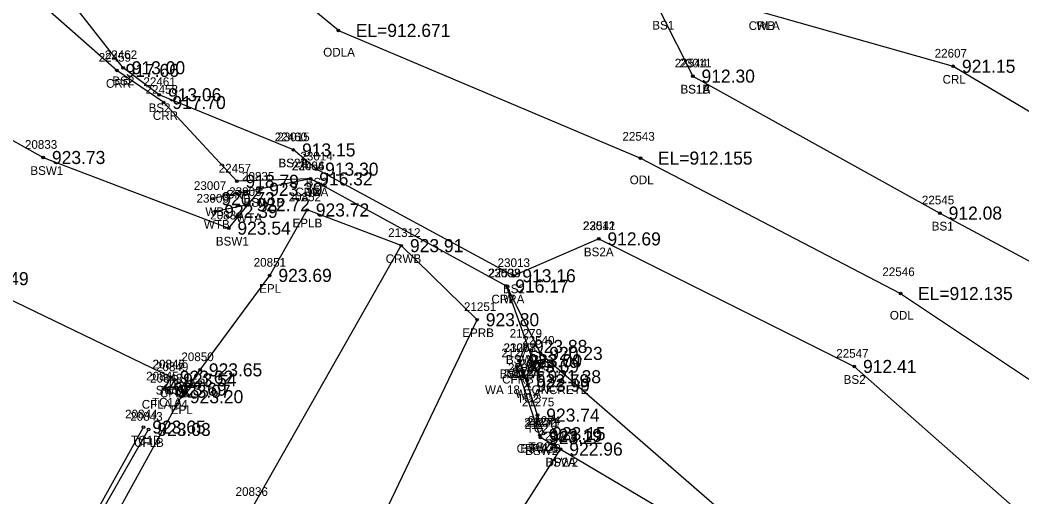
# Model space of a CAD drawing. Extents: x 1576181 to 1577685, y 1099396 to 1101490.
# Drawn here: x 1576844.5 to 1576959.6, y 1100377.3 to 1100432.1 of the extents above; entities that cross this region are included whole.
import ezdxf

# ---------------------------------------------------------------- set-up
doc = ezdxf.new("R2010")
doc.units = 0
for name, color, linetype in [('RD_DTM_BkLn1', 7, 'Continuous'), ('RD_DTM_BkLn2', 7, 'Continuous'), ('RD_DTM_BkLn_txCode', 7, 'Continuous'), ('RD_EX_BldgApp', 7, 'Continuous'), ('RD_EX_Conc', 7, 'Continuous'), ('RD_EX_Conc_txCode', 7, 'Continuous'), ('RD_EX_Driveway', 7, 'Continuous'), ('RD_EX_Driveway_txCode', 7, 'Continuous'), ('RD_EX_H2O', 7, 'Continuous'), ('RD_EX_H2O_txCode', 7, 'Continuous'), ('RD_EX_Misc_txCode', 7, 'Continuous'), ('RD_EX_Road', 7, 'Continuous'), ('RD_EX_Road_txCode', 7, 'Continuous'), ('RD_EX_TX_Conc_ELEV', 7, 'Continuous'), ('RD_EX_TX_Driveway_ELEV', 7, 'Continuous'), ('RD_EX_TX_H2O_ELEV', 7, 'Continuous'), ('RD_EX_TX_Misc_ELEV', 7, 'Continuous'), ('RD_EX_TX_Road_ELEV', 7, 'Continuous'), ('RD_HC_Survey_ELEV', 7, 'Continuous'), ('RD_HC_Survey_txCode', 7, 'Continuous'), ('RD_SMD_Locator', 7, 'Continuous')]:
    doc.layers.add(name, color=color, linetype=linetype)

msp = doc.modelspace()

# ---------------------------------------------------------------- linework, layer by layer
at = {"layer": 'RD_DTM_BkLn1'}
msp.add_lwpolyline([(1576435.96, 1099635.47), (1576469.98, 1099685.91), (1576496.51, 1099728.46), (1576522.67, 1099770.85), (1576549.06, 1099813.4), (1576563.36, 1099837.2), (1576575.09, 1099855.95), (1576600.75, 1099898.96), (1576625.57, 1099942.14), (1576652.37, 1099988.91), (1576675.03, 1100029.12), (1576699.51, 1100072.44), (1576723.52, 1100115.7), (1576748.08, 1100158.53), (1576774.13, 1100203.85), (1576797.97, 1100246.52), (1576822.46, 1100289.82), (1576846.93, 1100333.35), (1576871.37, 1100376.46), (1576888.27, 1100406.22)], dxfattribs=at)
at = {"layer": 'RD_DTM_BkLn2'}
for p, q in [((1576870.64, 1100410.93), (1576866.93, 1100410.16)), ((1576902.73, 1100390.7), (1576901.89, 1100392.99)), ((1576861.07, 1100389.73), (1576861.82, 1100391.11))]:
    msp.add_line(p, q, dxfattribs=at)
for points in [[(1576875.87, 1100417.22), (1576860.46, 1100423.56), (1576856.3, 1100426.66), (1576843.23, 1100443.4), (1576803.31, 1100463.52), (1576761.44, 1100493.57), (1576725.45, 1100515.73), (1576681.3, 1100547.02), (1576635.87, 1100579.97), (1576595.08, 1100610.51), (1576554.15, 1100644.81), (1576510.62, 1100680.61), (1576466.87, 1100717.7)], [(1576886.42, 1100451.57), (1576894.91, 1100444.78), (1576918.06, 1100433.05), (1576921.77, 1100425.7)], [(1576921.77, 1100425.7), (1576950.17, 1100409.96), (1576995.01, 1100385.92), (1577032.35, 1100355.75), (1577074.98, 1100332.75), (1577110.34, 1100313.04), (1577151.78, 1100294.62), (1577183.98, 1100273.41), (1577237.32, 1100241.27), (1577274.56, 1100213.94), (1577313.28, 1100186.77), (1577349.98, 1100171.96)], [(1576910.96, 1100407), (1576901.18, 1100402.76), (1576878.52, 1100415.01), (1576875.87, 1100417.22)], [(1576896.98, 1100397.71), (1576888.27, 1100406.22), (1576877.45, 1100410.32)], [(1576910.96, 1100407), (1576940.33, 1100392.34), (1576974.42, 1100362.26), (1577019.12, 1100334.75), (1577060.03, 1100308.77), (1577094.53, 1100282.76), (1577137.68, 1100262.43), (1577168.48, 1100246.28), (1577215.8, 1100216.27), (1577257.09, 1100185.27), (1577298.12, 1100162.18), (1577331.94, 1100143.39)], [(1576904.61, 1100384.62), (1576903.93, 1100386.75), (1576902.8, 1100390.19), (1576901.82, 1100392.99)], [(1576569.71, 1099889.13), (1576574.56, 1099891.34), (1576579.27, 1099894.47), (1576584.19, 1099899.55), (1576592.25, 1099913.59), (1576612.84, 1099949.87), (1576637.54, 1099993.05), (1576637.54, 1099993.05), (1576662.19, 1100036.34), (1576686.67, 1100079.69), (1576711.46, 1100123.12), (1576735.92, 1100166.59), (1576760.76, 1100210.19), (1576785.21, 1100253.55), (1576809.13, 1100296.43), (1576833.85, 1100340.61), (1576852.06, 1100373.52), (1576858.66, 1100385.37)]]:
    msp.add_lwpolyline(points, dxfattribs=at)
at = {"layer": 'RD_EX_BldgApp'}
msp.add_lwpolyline([(1576904.09, 1100391.16), (1576900.37, 1100401.58), (1576877.84, 1100413.89), (1576866.6, 1100411.62)], dxfattribs=at)
at = {"layer": 'RD_EX_Conc'}
for p, q in [((1576901.82, 1100392.99), (1576902.52, 1100394.64)), ((1576904.2, 1100384.42), (1576901.56, 1100392.38)), ((1576861.53, 1100389.49), (1576862.21, 1100390.8))]:
    msp.add_line(p, q, dxfattribs=at)
for points in [[(1576537.53, 1099904.47), (1576543.86, 1099909.52), (1576562.16, 1099910.99), (1576591.51, 1099962.44), (1576615.66, 1100005.02), (1576615.66, 1100005.02), (1576639.95, 1100047.65), (1576665.61, 1100092.87), (1576689.57, 1100135.17), (1576714.68, 1100179.66), (1576738.99, 1100222.53), (1576763.6, 1100265.87), (1576774.84, 1100284.48), (1576788.69, 1100308.17), (1576806.14, 1100353.34), (1576815.02, 1100384.28), (1576820.35, 1100399.92), (1576825.22, 1100406.93), (1576832.15, 1100418.17), (1576835.04, 1100423.11), (1576847.13, 1100416.35), (1576868.44, 1100408.23), (1576872.09, 1100412.69)], [(1576592.25, 1099913.59), (1576580.2, 1099912.49), (1576604.17, 1099954.86), (1576628.85, 1099997.89), (1576628.85, 1099997.89), (1576652.81, 1100040.47), (1576678.28, 1100085.17), (1576702.19, 1100127.32), (1576727.43, 1100172.04), (1576752.1, 1100215.39), (1576776.49, 1100258.76), (1576788, 1100277.34), (1576801.96, 1100301.42), (1576820.18, 1100348.3), (1576829.19, 1100379.59), (1576833.87, 1100393.41), (1576838.32, 1100402.43), (1576861.82, 1100391.11)], [(1576569.87, 1099888.69), (1576574.84, 1099890.86), (1576574.84, 1099890.86), (1576579.65, 1099894.15), (1576584.72, 1099899.29), (1576592.68, 1099913.3), (1576613.45, 1099949.72), (1576638.02, 1099992.78), (1576638.02, 1099992.78), (1576662.6, 1100036.05), (1576687.14, 1100079.44), (1576711.91, 1100122.93), (1576736.42, 1100166.35), (1576761.24, 1100209.96), (1576785.67, 1100253.17), (1576809.57, 1100296.25), (1576834.31, 1100340.56), (1576852.46, 1100373.22), (1576852.46, 1100373.22), (1576859.24, 1100385.1)], [(1576899.64, 1100371.95), (1576906.58, 1100382.84), (1576904.27, 1100384.16), (1576904.2, 1100384.42)]]:
    msp.add_lwpolyline(points, dxfattribs=at)
at = {"layer": 'RD_EX_Driveway'}
msp.add_lwpolyline([(1576906.58, 1100382.84), (1576964.44, 1100348.56), (1576998.21, 1100327.41)], dxfattribs=at)
at = {"layer": 'RD_EX_H2O'}
for points in [[(1576881.04, 1100430.95), (1576850.51, 1100456.18), (1576811.02, 1100474.55), (1576770.3, 1100506.51), (1576738.8, 1100537.68), (1576691.12, 1100558.51), (1576645.69, 1100592.61), (1576611.01, 1100637.34), (1576572.36, 1100669.07), (1576520.62, 1100693.32), (1576482.36, 1100733.93)], [(1576877.84, 1100413.89), (1576869.37, 1100413.62), (1576860.97, 1100422.67), (1576855.58, 1100426.36), (1576840.87, 1100439.31), (1576798.64, 1100456.7), (1576756.83, 1100486.11), (1576719.94, 1100507.6), (1576677.18, 1100540.85), (1576627.08, 1100575.48), (1576584.18, 1100605.6), (1576548.29, 1100637.23), (1576503.87, 1100673.91), (1576459.55, 1100707.51)], [(1576929.91, 1100433), (1576951.7, 1100426.83), (1576996.53, 1100400.27), (1577038.81, 1100373.75), (1577079.67, 1100350.15), (1577122.69, 1100322.64), (1577157.62, 1100301.09), (1577195.23, 1100276.28), (1577240.04, 1100251.66), (1577278.94, 1100221.51), (1577312.77, 1100200.12), (1577352.78, 1100176.91)], [(1576881.04, 1100430.95), (1576915.76, 1100416.28), (1576945.65, 1100400.72), (1576983.21, 1100375.69), (1577026.89, 1100346.5), (1577063.53, 1100313.12), (1577099, 1100292.55), (1577141.18, 1100270.15), (1577175.83, 1100258.35), (1577225.81, 1100228), (1577268.32, 1100204.5), (1577306.36, 1100176.14), (1577339.68, 1100156.23)], [(1576900.37, 1100401.58), (1576904.28, 1100393.84), (1576927.49, 1100373.64), (1576968.41, 1100349.92), (1577010.57, 1100322.36), (1577050.41, 1100297.37), (1577087.05, 1100275.19), (1577127.2, 1100251.29), (1577165.43, 1100227.76), (1577206.9, 1100201.89), (1577246.29, 1100176.81), (1577287.62, 1100151.2), (1577327.03, 1100134.92)]]:
    msp.add_lwpolyline(points, dxfattribs=at)
at = {"layer": 'RD_EX_Road'}
for points in [[(1576574.84, 1099890.86), (1576581.17, 1099887.16), (1576595.39, 1099911.97), (1576615.87, 1099948.17), (1576640.56, 1099991.4), (1576640.56, 1099991.4), (1576664.88, 1100034.19), (1576689.84, 1100078.06), (1576714.22, 1100121.19), (1576739.08, 1100164.66), (1576764.15, 1100209.11), (1576788.31, 1100251.8), (1576812.15, 1100294.46), (1576837.06, 1100339.37), (1576855.38, 1100371.53), (1576853.98, 1100372.48), (1576862.98, 1100388.86), (1576865.16, 1100391.95), (1576873.15, 1100402.8), (1576877.45, 1100410.32)], [(1576663.31, 1099979.53), (1576687.43, 1100021.53), (1576712.03, 1100065.1), (1576738.42, 1100112.14), (1576760.61, 1100151.41), (1576785.78, 1100195.96), (1576800.59, 1100221.87), (1576817.54, 1100252.08), (1576858.25, 1100324.63), (1576880.45, 1100364.01), (1576883.5, 1100369.45), (1576896.98, 1100397.71)]]:
    msp.add_lwpolyline(points, dxfattribs=at)
at = {"layer": 'RD_SMD_Locator'}
for centre in [(1576881.04, 1100430.95), (1576881.04, 1100430.95), (1576855.58, 1100426.36), (1576856.3, 1100426.66), (1576951.7, 1100426.83), (1576921.77, 1100425.7), (1576921.77, 1100425.7), (1576860.46, 1100423.56), (1576860.97, 1100422.67), (1576875.87, 1100417.22), (1576875.87, 1100417.22), (1576847.13, 1100416.35), (1576915.76, 1100416.28), (1576878.52, 1100415.01), (1576877.84, 1100413.89), (1576877.84, 1100413.89), (1576869.37, 1100413.62), (1576872.09, 1100412.69), (1576866.6, 1100411.62), (1576870.64, 1100410.93), (1576877.45, 1100410.32), (1576866.93, 1100410.16), (1576950.17, 1100409.96), (1576868.44, 1100408.23), (1576910.96, 1100407), (1576910.96, 1100407), (1576888.27, 1100406.22), (1576873.15, 1100402.8), (1576901.18, 1100402.76), (1576900.37, 1100401.58), (1576900.37, 1100401.58), (1576945.65, 1100400.72), (1576896.98, 1100397.71), (1576902.52, 1100394.64), (1576901.82, 1100392.99), (1576901.82, 1100392.99), (1576901.89, 1100392.99), (1576904.28, 1100393.84), (1576865.16, 1100391.95), (1576901.56, 1100392.38), (1576940.33, 1100392.34), (1576861.82, 1100391.11), (1576861.82, 1100391.11), (1576862.21, 1100390.8), (1576902.73, 1100390.7), (1576904.09, 1100391.16), (1576861.07, 1100389.73), (1576861.53, 1100389.49), (1576902.8, 1100390.19), (1576862.98, 1100388.86), (1576903.93, 1100386.75), (1576858.66, 1100385.37), (1576859.24, 1100385.1), (1576904.2, 1100384.42), (1576904.2, 1100384.42), (1576904.27, 1100384.16), (1576904.61, 1100384.62), (1576906.58, 1100382.84), (1576906.58, 1100382.84)]:
    msp.add_circle(centre, 0.15, dxfattribs=at)

# ---------------------------------------------------------------- texts
at = {"layer": 'RD_DTM_BkLn_txCode'}
for s, p in [('BS1', (1576917.11, 1100431.05)), ('22462', (1576854.2, 1100427.66)), ('22544', (1576919.69, 1100426.7)), ('23011', (1576920.22, 1100426.7)), ('BS2', (1576855.07, 1100424.66)), ('22461', (1576858.64, 1100424.56)), ('BS1A', (1576920.34, 1100423.7)), ('BS1B', (1576920.36, 1100423.7)), ('BS2', (1576859.23, 1100421.56)), ('22460', (1576873.73, 1100418.22)), ('23015', (1576874.03, 1100418.22)), ('BS2A', (1576874.15, 1100415.22)), ('BS2B', (1576874.17, 1100415.22)), ('23014', (1576876.68, 1100416.01)), ('BS2', (1576877.29, 1100413.01)), ('22545', (1576948.09, 1100410.96)), ('23012', (1576909.13, 1100408)), ('22541', (1576909.17, 1100408)), ('BS1', (1576949.22, 1100407.96)), ('BS2A', (1576909.25, 1100405)), ('BS2A', (1576909.25, 1100405)), ('23013', (1576899.34, 1100403.76)), ('BS2', (1576899.95, 1100400.76)), ('22547', (1576938.25, 1100393.34)), ('BS2', (1576939.1, 1100390.34))]:
    msp.add_text(s, height=1, dxfattribs=at).set_placement(p)
at = {"layer": 'RD_EX_Conc_txCode'}
for s, p in [('20833', (1576845.02, 1100417.35)), ('BSW1', (1576845.65, 1100414.35)), ('20835', (1576869.97, 1100413.69)), ('BSW1B', (1576870.14, 1100410.69)), ('20834', (1576866.32, 1100409.23)), ('BSW1', (1576866.96, 1100406.23)), ('21279', (1576900.73, 1100395.64)), ('21273', (1576899.77, 1100393.38)), ('21277', (1576900.03, 1100393.99)), ('21278', (1576900.03, 1100393.99)), ('20846', (1576859.68, 1100392.11)), ('20847', (1576859.7, 1100392.11)), ('BSW2B', (1576900.29, 1100392.64)), ('20849', (1576860.09, 1100391.8)), ('BSW2A', (1576899.57, 1100390.99)), ('TC2B', (1576900.11, 1100390.99)), ('21276', (1576900.98, 1100391.19)), ('20845', (1576858.95, 1100390.73)), ('20848', (1576859.41, 1100390.49)), ('CFRB', (1576899.86, 1100390.38)), ('SWLB', (1576860.06, 1100389.11)), ('TC1B', (1576860.39, 1100389.11)), ('CFLB', (1576860.53, 1100388.8)), ('CFLA 24', (1576858.45, 1100387.49)), ('TC1A', (1576859.62, 1100387.73)), ('TC2', (1576901.55, 1100388.19)), ('21275', (1576902.13, 1100387.75)), ('20844', (1576856.54, 1100386.37)), ('20843', (1576857.13, 1100386.1)), ('21272', (1576902.4, 1100385.42)), ('21270', (1576902.44, 1100385.16)), ('21271', (1576902.69, 1100385.42)), ('21274', (1576902.82, 1100385.62)), ('TC2', (1576902.68, 1100384.75)), ('TC1B', (1576857.22, 1100383.37)), ('CFLB', (1576857.57, 1100383.1)), ('21264', (1576904.76, 1100383.84)), ('CFRA 6', (1576901.52, 1100382.42)), ('BSW2B', (1576901.96, 1100382.42)), ('BSW2', (1576902.51, 1100382.16)), ('TC2A', (1576902.88, 1100382.62)), ('BSW2', (1576904.82, 1100380.84))]:
    msp.add_text(s, height=1, dxfattribs=at).set_placement(p)
at = {"layer": 'RD_EX_Driveway_txCode'}
for s, p in [('21265', (1576904.76, 1100383.84)), ('DP2A', (1576904.86, 1100380.84))]:
    msp.add_text(s, height=1, dxfattribs=at).set_placement(p)
at = {"layer": 'RD_EX_H2O_txCode'}
for s, p in [('CRLA', (1576928.19, 1100431)), ('ODLA', (1576879.3, 1100427.95)), ('ODLA', (1576879.3, 1100427.95)), ('22607', (1576949.56, 1100427.83)), ('22459', (1576853.5, 1100427.36)), ('CRR', (1576854.33, 1100424.36)), ('CRL', (1576950.47, 1100424.83)), ('22458', (1576858.89, 1100423.67)), ('CRR', (1576859.72, 1100420.67)), ('22543', (1576913.68, 1100418.28)), ('22457', (1576867.29, 1100414.62)), ('22456', (1576875.74, 1100414.89)), ('ODL', (1576914.52, 1100413.28)), ('CRRA', (1576876.1, 1100411.89)), ('CRR', (1576868.12, 1100411.62)), ('22539', (1576898.29, 1100402.58)), ('22546', (1576943.55, 1100402.72)), ('CRRA', (1576898.63, 1100399.58)), ('ODL', (1576944.41, 1100397.72)), ('22540', (1576902.16, 1100394.84)), ('CRR', (1576903.03, 1100391.84))]:
    msp.add_text(s, height=1, dxfattribs=at).set_placement(p)
at = {"layer": 'RD_EX_Misc_txCode'}
for s, p in [('WB', (1576929.07, 1100431)), ('23004', (1576875.69, 1100414.89)), ('23007', (1576864.44, 1100412.62)), ('23005', (1576868.49, 1100411.93)), ('W', (1576877.47, 1100411.89)), ('23006', (1576864.74, 1100411.16)), ('WB', (1576865.76, 1100409.62)), ('WTA', (1576869.3, 1100408.93)), ('WTB', (1576865.59, 1100408.16)), ('23003', (1576898.21, 1100402.58)), ('W', (1576900, 1100399.58)), ('23001', (1576900.01, 1100393.99)), ('23002', (1576901.93, 1100392.16)), ('WTB', (1576900.56, 1100390.99)), ('23000', (1576900.53, 1100391.7)), ('WA 18 CONCRETE', (1576897.89, 1100389.16)), ('WTA', (1576901.38, 1100388.7))]:
    msp.add_text(s, height=1, dxfattribs=at).set_placement(p)
at = {"layer": 'RD_EX_Road_txCode'}
for s, p in [('20852', (1576875.33, 1100411.32)), ('EPLB', (1576875.77, 1100408.32)), ('20851', (1576871.31, 1100403.8)), ('EPL', (1576871.94, 1100400.8)), ('21251', (1576895.47, 1100398.71)), ('EPRB', (1576895.28, 1100395.71)), ('20850', (1576863, 1100392.95)), ('20842', (1576860.87, 1100389.86)), ('EPL', (1576863.96, 1100389.95)), ('EPL', (1576861.78, 1100386.86))]:
    msp.add_text(s, height=1, dxfattribs=at).set_placement(p)
at = {"layer": 'RD_EX_TX_Conc_ELEV'}
for s, p in [('923.73', (1576848.13, 1100415.6)), ('923.39', (1576873.09, 1100411.94)), ('923.54', (1576869.44, 1100407.48)), ('923.49', (1576839.32, 1100401.68)), ('923.88', (1576903.52, 1100393.89)), ('923.69', (1576902.56, 1100391.63)), ('923.74', (1576902.82, 1100392.24)), ('923.74', (1576902.82, 1100392.24)), ('923.62', (1576862.82, 1100390.36)), ('923.62', (1576862.82, 1100390.36)), ('923.54', (1576863.21, 1100390.05)), ('923.99', (1576903.8, 1100389.44)), ('923.69', (1576862.07, 1100388.98)), ('923.07', (1576862.53, 1100388.74)), ('923.74', (1576904.93, 1100386)), ('923.65', (1576859.66, 1100384.62)), ('923.03', (1576860.24, 1100384.35)), ('923.19', (1576905.2, 1100383.67)), ('923.19', (1576905.2, 1100383.67)), ('923.15', (1576905.61, 1100383.87)), ('923.22', (1576905.27, 1100383.41)), ('922.96', (1576907.58, 1100382.09))]:
    msp.add_text(s, height=1.5, dxfattribs=at).set_placement(p)
at = {"layer": 'RD_EX_TX_Driveway_ELEV'}
msp.add_text('922.96', height=1.5, dxfattribs=at).set_placement((1576907.58, 1100382.09))
at = {"layer": 'RD_EX_TX_H2O_ELEV'}
for s, p in [('EL=912.671', (1576883.04, 1100430.2)), ('EL=912.671', (1576883.04, 1100430.2)), ('917.66', (1576856.58, 1100425.61)), ('921.15', (1576952.7, 1100426.08)), ('917.70', (1576861.97, 1100421.92)), ('EL=912.155', (1576917.76, 1100415.53)), ('918.79', (1576870.37, 1100412.87)), ('916.32', (1576878.84, 1100413.14)), ('916.17', (1576901.37, 1100400.83)), ('EL=912.135', (1576947.65, 1100399.97)), ('920.23', (1576905.28, 1100393.09))]:
    msp.add_text(s, height=1.5, dxfattribs=at).set_placement(p)
at = {"layer": 'RD_EX_TX_Misc_ELEV'}
for s, p in [('913.00', (1576857.3, 1100425.91)), ('912.30', (1576922.77, 1100424.95)), ('912.30', (1576922.77, 1100424.95)), ('913.06', (1576861.46, 1100422.81)), ('913.15', (1576876.87, 1100416.47)), ('913.15', (1576876.87, 1100416.47)), ('913.30', (1576879.52, 1100414.26)), ('916.32', (1576878.84, 1100413.14)), ('920.73', (1576867.6, 1100410.87)), ('922.72', (1576871.64, 1100410.18)), ('922.39', (1576867.93, 1100409.41)), ('912.08', (1576951.17, 1100409.21)), ('912.69', (1576911.96, 1100406.25)), ('912.69', (1576911.96, 1100406.25)), ('913.16', (1576902.18, 1100402.01)), ('916.17', (1576901.37, 1100400.83)), ('923.00', (1576902.89, 1100392.24)), ('912.41', (1576941.33, 1100391.59)), ('921.38', (1576905.09, 1100390.41)), ('922.79', (1576903.73, 1100389.95))]:
    msp.add_text(s, height=1.5, dxfattribs=at).set_placement(p)
at = {"layer": 'RD_EX_TX_Road_ELEV'}
for s, p in [('923.72', (1576878.45, 1100409.57)), ('923.69', (1576874.15, 1100402.05)), ('923.80', (1576897.98, 1100396.96)), ('923.65', (1576866.16, 1100391.2)), ('923.20', (1576863.98, 1100388.11))]:
    msp.add_text(s, height=1.5, dxfattribs=at).set_placement(p)
at = {"layer": 'RD_HC_Survey_ELEV'}
msp.add_text('923.91', height=1.5, dxfattribs=at).set_placement((1576889.27, 1100405.47))
at = {"layer": 'RD_HC_Survey_txCode'}
for s, p in [('21312', (1576886.76, 1100407.22)), ('CRWB', (1576886.48, 1100404.22)), ('20836', (1576869.23, 1100377.46))]:
    msp.add_text(s, height=1, dxfattribs=at).set_placement(p)

doc.saveas('drawing.dxf')
